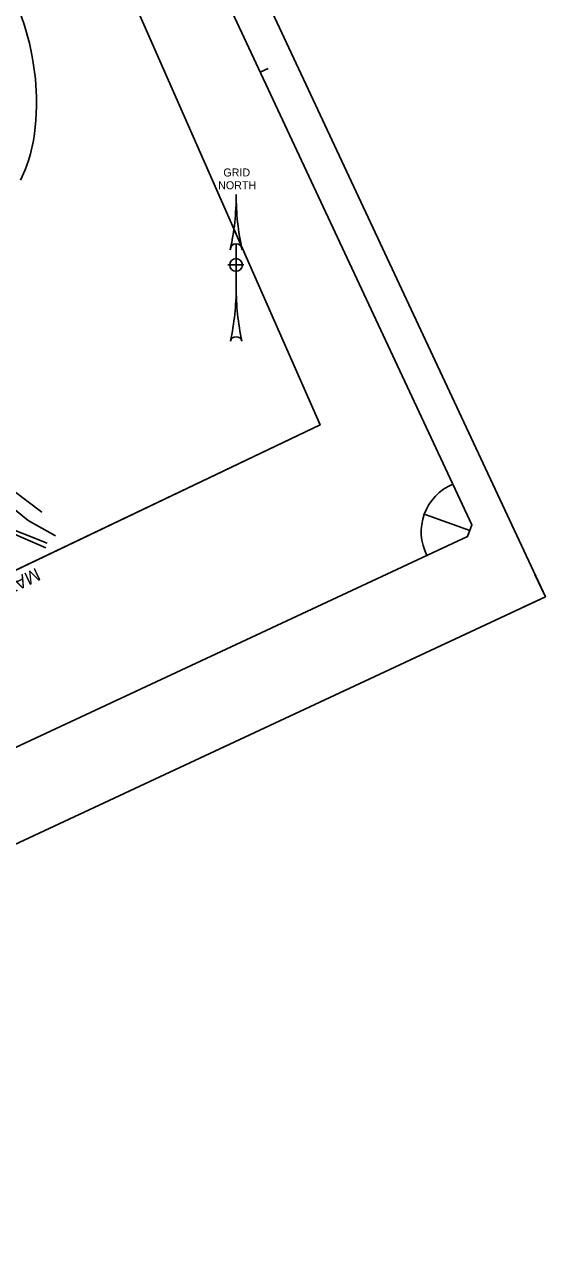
# Model space of a CAD drawing. Extents: x 1040814 to 1041501, y 1126274 to 1127077.
# Drawn here: x 1041352.2 to 1041500.7, y 1126274.4 to 1126623.9 of the extents above; entities that cross this region are included whole.
import ezdxf

# ---------------------------------------------------------------- set-up
doc = ezdxf.new("R2010")
doc.units = 0
for name, color, linetype in [('clip boundary', 7, 'Continuous'), ('LAWE', 7, 'Continuous'), ('LELB', 7, 'Continuous'), ('NML_P', 7, 'Continuous'), ('NML_P_T', 7, 'Continuous'), ('NNA_P', 7, 'Continuous'), ('RDU', 7, 'Continuous'), ('SHEET_BORDER', 7, 'Continuous'), ('SHEET_BORDER_CUT', 7, 'Continuous')]:
    doc.layers.add(name, color=color, linetype=linetype)

msp = doc.modelspace()

# ---------------------------------------------------------------- linework, layer by layer
at = {"layer": 'clip boundary'}
for points in [[(1041212.91, 1127076.67), (1041500.71, 1126460.57), (1041102.06, 1126274.35), (1040814.26, 1126890.45)], [(1041214.88, 1127013.05), (1041436.47, 1126509.64), (1041196.3, 1126394.87), (1040940.57, 1126882.48)]]:
    msp.add_lwpolyline(points, close=True, dxfattribs=at)
at = {"layer": 'LAWE'}
msp.add_lwpolyline([(1041358.27, 1126474.52), (1041345.09, 1126480.29), (1041333.52, 1126486.04), (1041329.31, 1126492.15), (1041324.1, 1126498.5), (1041319.97, 1126503.98), (1041313.58, 1126506.41)], dxfattribs=at)
at = {"layer": 'LELB'}
for points in [[(1041334.37, 1126460.85), (1041326.46, 1126467.11), (1041317.72, 1126475.49), (1041315.51, 1126480.89), (1041312.47, 1126486.91), (1041308.79, 1126491.43), (1041307.3, 1126499), (1041309.01, 1126501.86), (1041310.14, 1126503.62), (1041311.9, 1126506.77), (1041314.86, 1126508.46), (1041317.98, 1126508.18), (1041322.26, 1126506.19), (1041326.05, 1126505.01), (1041337.16, 1126499.74), (1041357.15, 1126484.76)], [(1041358.63, 1126475.84), (1041345.13, 1126481.25), (1041333.9, 1126486.59), (1041329.81, 1126492.61), (1041325, 1126499.74), (1041320.38, 1126504.55), (1041313.58, 1126506.41)], [(1041326.28, 1126502.08), (1041337.5, 1126495.77), (1041345.92, 1126488.36), (1041353.29, 1126482.37), (1041361.08, 1126477.94)]]:
    msp.add_lwpolyline(points, dxfattribs=at)
at = {"layer": 'NML_P'}
msp.add_line((1041196.3, 1126394.87), (1041436.47, 1126509.64), dxfattribs=at)
at = {"layer": 'NNA_P'}
for p, q in [((1041412.55, 1126548.91), (1041412.55, 1126561.28)), ((1041410.21, 1126555.26), (1041414.76, 1126555.26))]:
    msp.add_line(p, q, dxfattribs=at)
msp.add_circle((1041412.52, 1126555.28), 1.81, dxfattribs=at)
for centre, radius, start, end in [((1041339.46, 1126575.22), 73.09, 347.6515, 0.1139), ((1041485.63, 1126575.22), 73.09, 179.8844, 192.3468), ((1041412.54, 1126559.59), 1.69, 359.9991, 179.9991), ((1041339.46, 1126548.89), 73.09, 347.8917, 0.0159), ((1041485.63, 1126548.89), 73.09, 179.9824, 192.1066), ((1041412.54, 1126533.09), 1.69, 15.894, 164.1052)]:
    msp.add_arc(centre, radius, start, end, dxfattribs=at)
at = {"layer": 'RDU'}
msp.add_lwpolyline([(1041351.08, 1126579.43), (1041352.38, 1126582.35), (1041353.35, 1126585.08), (1041353.9, 1126586.95), (1041354.75, 1126590.75), (1041355.07, 1126592.68), (1041355.48, 1126596.59), (1041355.65, 1126600.52), (1041355.62, 1126603.15), (1041355.3, 1126608.36), (1041354.72, 1126612.93), (1041354.33, 1126615.19), (1041353.62, 1126618.54), (1041352.25, 1126623.54), (1041350.5, 1126628.52)], dxfattribs=at)
at = {"layer": 'SHEET_BORDER'}
msp.add_line((1041419.41, 1126610.23), (1041421.68, 1126611.29), dxfattribs=at)
msp.add_lwpolyline([(1041103.08, 1126302.42), (1041099.76, 1126303.63), (1040835.24, 1126869.9), (1040836.45, 1126873.22), (1041211.88, 1127048.6), (1041215.2, 1127047.39), (1041479.72, 1126481.12), (1041478.52, 1126477.8)], close=True, dxfattribs=at)
msp.add_lwpolyline([(1041479.12, 1126479.46), (1041466.39, 1126484.09)], dxfattribs=at)
msp.add_arc((1041480.07, 1126479.12), 14.79, 112.9605, 207.117, dxfattribs=at)
at = {"layer": 'SHEET_BORDER_CUT'}
msp.add_lwpolyline([(1040814.26, 1126890.45), (1041102.06, 1126274.35), (1041500.71, 1126460.57), (1041212.91, 1127076.67)], close=True, dxfattribs=at)
msp.add_lwpolyline([(1041497.71, 1126466.98), (1041500.71, 1126460.57), (1041494.3, 1126457.58)], dxfattribs=at)

# ---------------------------------------------------------------- texts
at = {"layer": 'NML_P_T'}
msp.add_text('MATCHLINE STA. 18+50 - SEE DWG. GNP-05', height=3.744, rotation=205.541, dxfattribs=at).set_placement((1041355.53, 1126468.94))
at = {"layer": 'NNA_P'}
for s, p in [('GRID', (1041408.88, 1126580.5)), ('NORTH', (1041407.4, 1126576.85))]:
    msp.add_text(s, height=2.283, rotation=359.9991, dxfattribs=at).set_placement(p)

doc.saveas('drawing.dxf')
